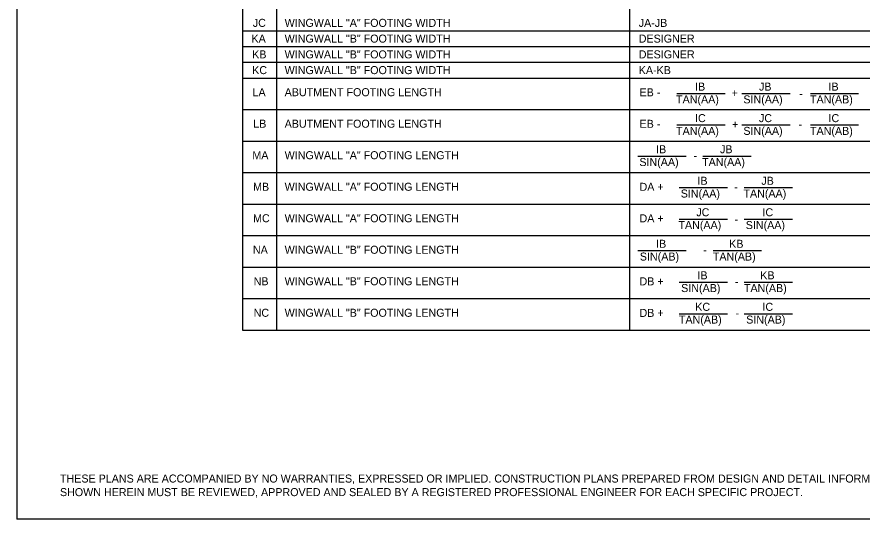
# Model space of a CAD drawing. Extents: x -5022 to -159, y 1126 to 7226.
# Drawn here: x -1277.1 to -960.5, y 6487.1 to 6675.4 of the extents above; entities that cross this region are included whole.
import ezdxf

# ---------------------------------------------------------------- set-up
doc = ezdxf.new("R2010")
doc.units = 0
doc.layers.add('2', color=7, linetype='Continuous')
doc.layers.add('5', color=7, linetype='Continuous')

msp = doc.modelspace()

# ---------------------------------------------------------------- linework, layer by layer
at = {"layer": '2'}
for p, q in [((-1277.13, 7051.14), (-1277.13, 6487.14)), ((-1029.83, 6646.68), (-1011.77, 6646.68)), ((-1005.47, 6646.68), (-987.41, 6646.68)), ((-979.83, 6646.68), (-961.77, 6646.68)), ((-1029.83, 6634.87), (-1011.77, 6634.87)), ((-1005.47, 6634.87), (-987.41, 6634.87)), ((-979.83, 6634.87), (-961.77, 6634.87)), ((-1044.43, 6623.2), (-1026.38, 6623.2)), ((-1020.07, 6623.2), (-1002.01, 6623.2)), ((-1028.94, 6611.39), (-1010.88, 6611.39)), ((-1004.58, 6611.39), (-986.52, 6611.39)), ((-1028.94, 6599.58), (-1010.88, 6599.58)), ((-1004.58, 6599.58), (-986.52, 6599.58)), ((-1044.43, 6587.76), (-1026.38, 6587.76)), ((-1016.23, 6587.76), (-998.17, 6587.76)), ((-1028.94, 6575.95), (-1010.88, 6575.95)), ((-1004.58, 6575.95), (-986.52, 6575.95)), ((-1028.94, 6564.14), (-1010.88, 6564.14)), ((-1004.58, 6564.14), (-986.52, 6564.14)), ((-491.13, 6487.14), (-1277.13, 6487.14))]:
    msp.add_line(p, q, dxfattribs=at)
at = {"layer": '5'}
for p, q in [((-1192.63, 7033.07), (-1192.63, 6557.97)), ((-1179.84, 6859.16), (-1179.84, 6557.97)), ((-1047.56, 6859.16), (-1047.56, 6557.97)), ((-1192.63, 6670.18), (-817, 6670.18)), ((-1192.63, 6664.27), (-817, 6664.27)), ((-1192.63, 6658.36), (-817, 6658.36)), ((-1192.63, 6652.46), (-817, 6652.46)), ((-1192.63, 6640.65), (-817, 6640.65)), ((-1192.63, 6628.84), (-817, 6628.84)), ((-1192.63, 6617.02), (-817, 6617.02)), ((-1192.63, 6605.21), (-817, 6605.21)), ((-1192.63, 6593.4), (-817, 6593.4)), ((-1192.63, 6581.59), (-817, 6581.59)), ((-1192.63, 6569.78), (-817, 6569.78)), ((-1192.63, 6557.97), (-817, 6557.97))]:
    msp.add_line(p, q, dxfattribs=at)

# ---------------------------------------------------------------- texts
at = {"layer": '2'}
for s, height, p in [('JC', 3, (-1188.74, 6671.65)), ('WINGWALL "A" FOOTING WIDTH', 3.0001, (-1176.81, 6671.65)), ('JA-JB', 3, (-1044.14, 6671.65)), ('KA', 3, (-1189.23, 6665.75)), ('WINGWALL "B" FOOTING WIDTH', 3.0001, (-1176.81, 6665.75)), ('DESIGNER', 3, (-1044.14, 6665.75)), ('WINGWALL "B" FOOTING WIDTH', 3.0001, (-1176.81, 6659.84)), ('DESIGNER', 3, (-1044.14, 6659.84)), ('KB', 3, (-1188.97, 6659.84)), ('KC', 3, (-1188.97, 6653.94)), ('WINGWALL "B" FOOTING WIDTH', 3.0001, (-1176.81, 6653.94)), ('KA-KB', 3, (-1044.14, 6653.94)), ('IB', 3, (-1023.04, 6647.75)), ('JB', 3, (-999.09, 6647.75)), ('IB', 3, (-973.04, 6647.75)), ('LA', 3, (-1188.84, 6645.66)), ('ABUTMENT FOOTING LENGTH', 3.0001, (-1176.81, 6645.66)), ('EB -', 3, (-1043.85, 6645.62)), ('+', 3, (-1009.33, 6645.38)), ('TAN(AA)', 3, (-1030.16, 6642.97)), ('SIN(AA)', 3, (-1004.94, 6642.97)), ('-', 3, (-983.98, 6645.18)), ('TAN(AB)', 3, (-979.98, 6642.97)), ('IC', 3, (-1023.04, 6635.94)), ('JC', 3, (-999.1, 6635.94)), ('IC', 3, (-973.04, 6635.94)), ('LB', 3, (-1188.58, 6633.85)), ('ABUTMENT FOOTING LENGTH', 3.0001, (-1176.81, 6633.85)), ('EB -', 3, (-1043.85, 6633.81)), ('+', 3, (-1009.18, 6633.62)), ('-', 3, (-984.28, 6633.67)), ('TAN(AA)', 3, (-1030.16, 6631.16)), ('SIN(AA)', 3, (-1004.94, 6631.16)), ('TAN(AB)', 3, (-979.98, 6631.16)), ('MA', 3, (-1188.9, 6622.04)), ('WINGWALL "A" FOOTING LENGTH', 3.0001, (-1176.81, 6622.04)), ('IB', 3, (-1037.64, 6624.27)), ('JB', 3, (-1013.7, 6624.27)), ('SIN(AA)', 3, (-1043.91, 6619.49)), ('-', 3, (-1023.57, 6621.86)), ('TAN(AA)', 3, (-1020.4, 6619.49)), ('IB', 3, (-1022.15, 6612.46)), ('JB', 3, (-998.21, 6612.46)), ('MB', 3, (-1188.64, 6610.22)), ('WINGWALL "A" FOOTING LENGTH', 3.0001, (-1176.81, 6610.22)), ('DA +', 3, (-1043.85, 6610.19)), ('SIN(AA)', 3, (-1028.42, 6607.68)), ('-', 3, (-1008.35, 6610.12)), ('TAN(AA)', 3, (-1004.91, 6607.68)), ('JC', 3, (-1022.58, 6600.65)), ('IC', 3, (-997.79, 6600.65)), ('MC', 3, (-1188.64, 6598.41)), ('WINGWALL "A" FOOTING LENGTH', 3.0001, (-1176.81, 6598.41)), ('DA +', 3, (-1043.85, 6598.38)), ('TAN(AA)', 3, (-1029.27, 6595.87)), ('-', 3, (-1008.22, 6598.03)), ('SIN(AA)', 3, (-1004.05, 6595.87)), ('IB', 3, (-1037.64, 6588.84)), ('KB', 3, (-1010.25, 6588.84)), ('NA', 3, (-1188.69, 6586.6)), ('WINGWALL "B" FOOTING LENGTH', 3.0001, (-1176.81, 6586.6)), ('SIN(AB)', 3, (-1043.73, 6584.05)), ('-', 3, (-1020, 6586.56)), ('TAN(AB)', 3, (-1016.38, 6584.05)), ('NB', 3, (-1188.43, 6574.79)), ('WINGWALL "B" FOOTING LENGTH', 3.0001, (-1176.81, 6574.79)), ('DB +', 3, (-1043.85, 6574.75)), ('IB', 3, (-1022.15, 6577.03)), ('KB', 3, (-998.6, 6577.03)), ('SIN(AB)', 3, (-1028.24, 6572.24)), ('-', 3, (-1008.08, 6574.68)), ('TAN(AB)', 3, (-1004.73, 6572.24)), ('KC', 3, (-1022.97, 6565.21)), ('IC', 3, (-997.79, 6565.21)), ('NC', 3, (-1188.43, 6562.98)), ('WINGWALL "B" FOOTING LENGTH', 3.0001, (-1176.81, 6562.98)), ('DB +', 3, (-1043.85, 6562.94)), ('TAN(AB)', 3, (-1029.1, 6560.43)), ('-', 3, (-1007.87, 6562.87)), ('SIN(AB)', 3, (-1003.88, 6560.43)), ('THESE PLANS ARE ACCOMPANIED BY NO WARRANTIES, EXPRESSED OR IMPLIED. CONSTRUCTION PLANS PREPARED FROM DESIGN AND DETAIL INFORMATION', 3.00008, (-1261, 6500.84)), ('SHOWN HEREIN MUST BE REVIEWED, APPROVED AND SEALED BY A REGISTERED PROFESSIONAL ENGINEER FOR EACH SPECIFIC PROJECT.', 3.00008, (-1261, 6495.75))]:
    msp.add_text(s, height=height, dxfattribs=at).set_placement(p)

doc.saveas('drawing.dxf')
